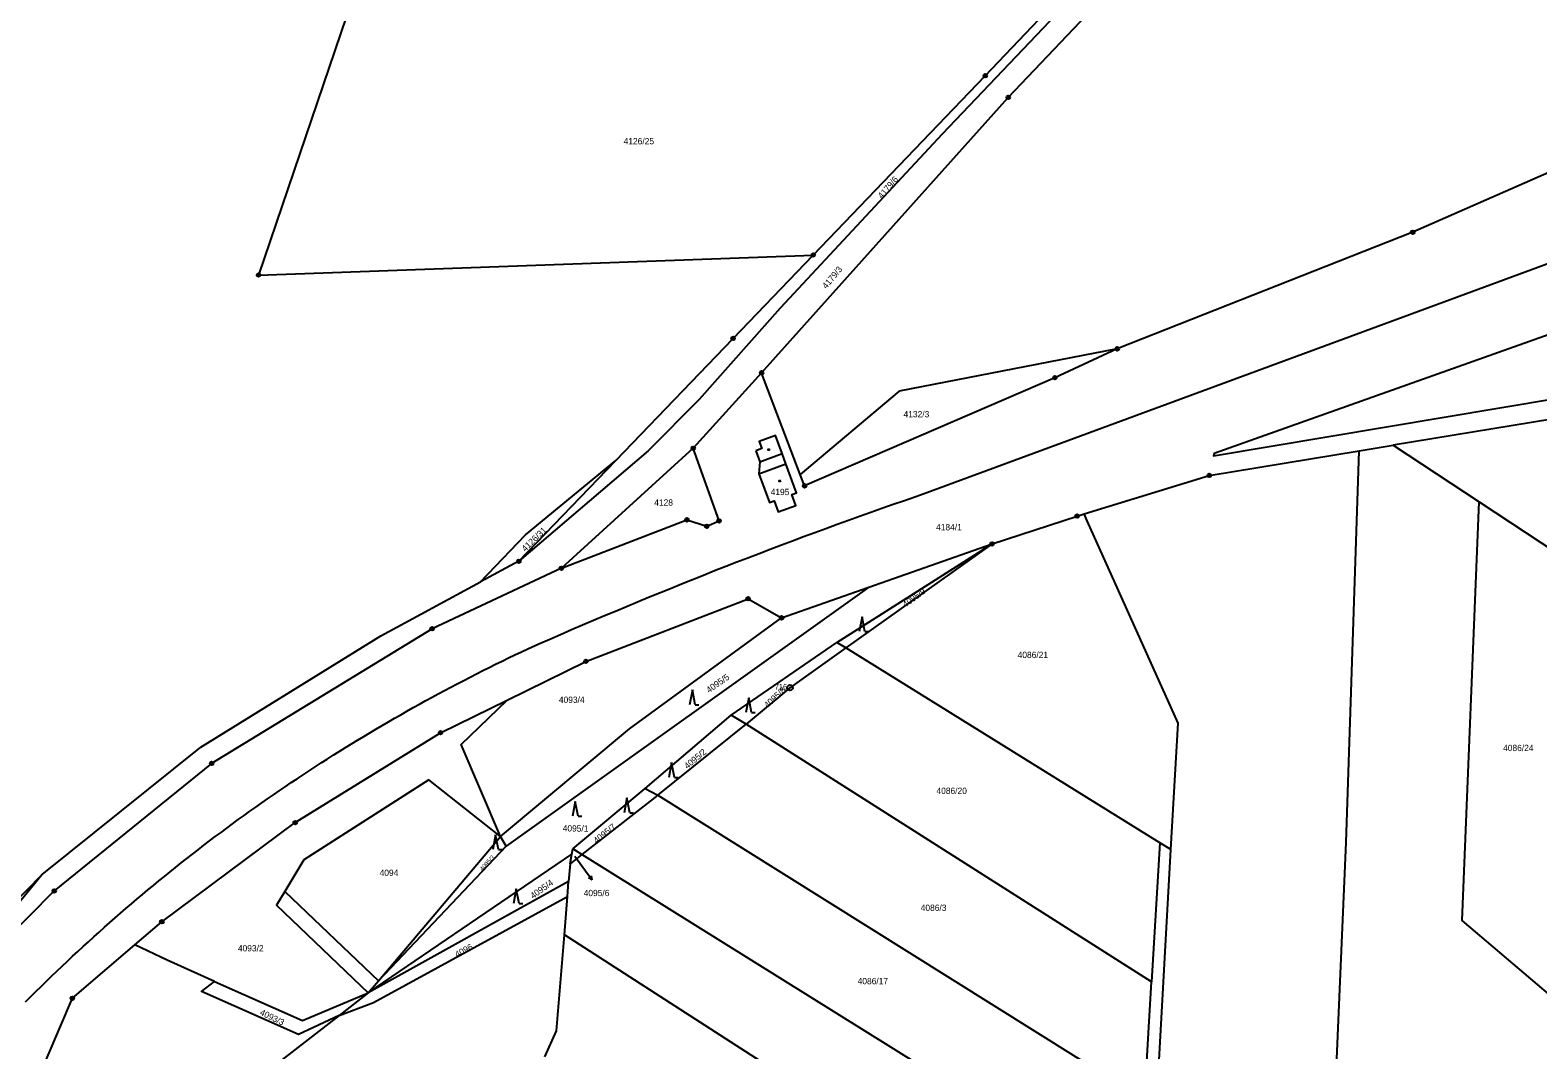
# Model space of a CAD drawing. Extents: x -733394 to -722299, y -1082822 to -1075049.
# Drawn here: x -729569.1 to -729161.7, y -1081847.7 to -1081571.9 of the extents above; entities that cross this region are included whole.
import ezdxf

# ---------------------------------------------------------------- set-up
doc = ezdxf.new("R2010")
doc.units = 0
for name, color, linetype in [('Hranice parcel', 7, 'Continuous'), ('Parcelní čísla', 7, 'Continuous'), ('Pop  PČ popisy', 7, 'Continuous'), ('Poz předměty', 7, 'Continuous'), ('Vnitřní kresba', 7, 'Continuous'), ('Značky bodu BP', 7, 'Continuous'), ('Značky budov', 7, 'Continuous'), ('Značky kultur', 7, 'Continuous')]:
    doc.layers.add(name, color=color, linetype=linetype)

msp = doc.modelspace()

# ---------------------------------------------------------------- linework, layer by layer
at = {"layer": 'Hranice parcel'}
for p, q in [((-729371.44, -1081664.57), (-729389.9, -1081684.99)), ((-729360.98, -1081692.11), (-729371.44, -1081664.57)), ((-729147.09, -1081675.32), (-729200.74, -1081684.15)), ((-729389.9, -1081684.99), (-729425.54, -1081717.43)), ((-729250.47, -1081692.34), (-729209.9, -1081685.66)), ((-729209.9, -1081685.66), (-729200.74, -1081684.15)), ((-729200.74, -1081684.15), (-729177.53, -1081699.5)), ((-729437.01, -1081715.56), (-729410.82, -1081688.29)), ((-729284.29, -1081702.76), (-729250.47, -1081692.34)), ((-729177.53, -1081699.5), (-729146.35, -1081720.13)), ((-729351.06, -1081737.52), (-729309.14, -1081710.85)), ((-729309.14, -1081710.85), (-729348.68, -1081739)), ((-729342.42, -1081722.55), (-729309.14, -1081710.85)), ((-729437.01, -1081715.56), (-729447.39, -1081721.16)), ((-729342.42, -1081722.55), (-729440.43, -1081792.62)), ((-729366.02, -1081730.85), (-729342.42, -1081722.55)), ((-729379.64, -1081757.19), (-729351.06, -1081737.52)), ((-729348.68, -1081739), (-729351.06, -1081737.52)), ((-729263.79, -1081791.67), (-729348.68, -1081739)), ((-729402.86, -1081777.01), (-729379.64, -1081757.19)), ((-729399.46, -1081778.81), (-729375.64, -1081759.59)), ((-729375.64, -1081759.59), (-729379.64, -1081757.19)), ((-729266.02, -1081829.3), (-729375.64, -1081759.59)), ((-729520.09, -1081770.22), (-729562.59, -1081804.71)), ((-729422.44, -1081793.36), (-729402.86, -1081777.01)), ((-729399.46, -1081778.81), (-729419.98, -1081794.89)), ((-729402.86, -1081777.01), (-729399.46, -1081778.81)), ((-729399.46, -1081778.81), (-729267.91, -1081861.15)), ((-729474.96, -1081828.97), (-729442.01, -1081790.02)), ((-729440.43, -1081792.62), (-729474.96, -1081828.97)), ((-729440.43, -1081792.62), (-729442.01, -1081790.02)), ((-729263.79, -1081791.67), (-729266.02, -1081829.3)), ((-729260.87, -1081793.48), (-729263.79, -1081791.67)), ((-729477.74, -1081832.25), (-729422.71, -1081794.79)), ((-729423.2, -1081797.41), (-729422.71, -1081794.79)), ((-729419.98, -1081794.89), (-729423.2, -1081797.41)), ((-729422.71, -1081794.79), (-729422.44, -1081793.36)), ((-729419.98, -1081794.89), (-729422.44, -1081793.36)), ((-729269.54, -1081888.64), (-729419.98, -1081794.89)), ((-729266.63, -1081899.59), (-729260.87, -1081793.48)), ((-729423.2, -1081797.41), (-729423.58, -1081802.17)), ((-729423.58, -1081802.17), (-729477.74, -1081832.25)), ((-729423.91, -1081806.25), (-729423.58, -1081802.17)), ((-729424.74, -1081816.55), (-729423.91, -1081806.25)), ((-729281.65, -1081908.79), (-729424.74, -1081816.55)), ((-729477.74, -1081832.25), (-729474.96, -1081828.97)), ((-729267.91, -1081861.15), (-729266.02, -1081829.3)), ((-729477.74, -1081832.25), (-729485.64, -1081838.38)), ((-729485.64, -1081838.38), (-729521.77, -1081866.42))]:
    msp.add_line(p, q, dxfattribs=at)
for points in [[(-729371.44, -1081664.57), (-729304.79, -1081590.12), (-729217.98, -1081498.78), (-729212.82, -1081482.72), (-729195.69, -1081383.64)], [(-729219.43, -1081482.86), (-729223.29, -1081496.17), (-729268.21, -1081542.86), (-729322.66, -1081600.05), (-729366.41, -1081647.14), (-729388.35, -1081671.83), (-729402.11, -1081685.74), (-729437.01, -1081715.56)], [(-728955.52, -1081524.35), (-728958.04, -1081525.39), (-729072.47, -1081572.57), (-729195.44, -1081626.58), (-729275.3, -1081658.11)], [(-729474.06, -1081539.95), (-729507.39, -1081638.15), (-729357.49, -1081632.74)], [(-729357.49, -1081632.74), (-729311, -1081584.27), (-729278.36, -1081549.84)], [(-729126.88, -1081658.24), (-729059.55, -1081636.73), (-729063.72, -1081620.5), (-729249.1, -1081686.45), (-729249.27, -1081687.01), (-729125.18, -1081666.25), (-729126.88, -1081658.24)], [(-729410.82, -1081688.29), (-729379.13, -1081655.3), (-729357.49, -1081632.74)], [(-729275.3, -1081658.11), (-729292.18, -1081665.91), (-729359.82, -1081695.16), (-729360.98, -1081692.11)], [(-729275.3, -1081658.11), (-729334.28, -1081669.53), (-729360.98, -1081692.11)], [(-729372.99, -1081685.69), (-729371.87, -1081688.68), (-729372.16, -1081691.92), (-729369.26, -1081699.71), (-729368.02, -1081699.25), (-729366.92, -1081702.21), (-729362.19, -1081700.44), (-729363.23, -1081697.47), (-729362, -1081697.01), (-729364.91, -1081689.21), (-729365.92, -1081686.46), (-729367.72, -1081681.58), (-729372.06, -1081683.2), (-729371.36, -1081685.07), (-729372.99, -1081685.69)], [(-729425.54, -1081717.43), (-729391.62, -1081704.35), (-729386.28, -1081706.1), (-729382.91, -1081704.64), (-729389.9, -1081684.99)], [(-729225.08, -1082061.1), (-729213.41, -1081791.58), (-729209.9, -1081685.66)], [(-729447.39, -1081721.16), (-729435.27, -1081708.4), (-729410.82, -1081688.29)], [(-729309.14, -1081710.85), (-729286.17, -1081703.34), (-729284.29, -1081702.76)], [(-729260.87, -1081793.48), (-729258.83, -1081759.33), (-729283.41, -1081704.6), (-729284.29, -1081702.76)], [(-729151.56, -1081838.69), (-729182.1, -1081812.72), (-729177.53, -1081699.5)], [(-729425.54, -1081717.43), (-729460.49, -1081733.82), (-729520.09, -1081770.22)], [(-729565.86, -1081800.28), (-729522.98, -1081765.86), (-729474.37, -1081735.71), (-729447.39, -1081721.16)], [(-729440.23, -1081753.09), (-729418.91, -1081742.62), (-729375.08, -1081725.68), (-729366.02, -1081730.85)], [(-729442.01, -1081790.02), (-729407.18, -1081760.91), (-729366.02, -1081730.85)], [(-729348.68, -1081739), (-729363.77, -1081749.74), (-729375.64, -1081759.59)], [(-729540.82, -1081819.28), (-729533.52, -1081813.03), (-729497.48, -1081786.24), (-729458.18, -1081761.91), (-729440.23, -1081753.09)], [(-729442.01, -1081790.02), (-729452.66, -1081765.14), (-729440.23, -1081753.09)], [(-729442.01, -1081790.02), (-729461.38, -1081774.69), (-729495.12, -1081796.26), (-729500.27, -1081804.82), (-729502.5, -1081808.52), (-729477.74, -1081832.25)], [(-729604.28, -1081845.42), (-729594.92, -1081829.92), (-729565.86, -1081800.28)], [(-729565.86, -1081800.28), (-729588.27, -1081827.56), (-729604.28, -1081845.42)], [(-729562.59, -1081804.71), (-729590.89, -1081833.28), (-729600.23, -1081846.76)], [(-729485.64, -1081838.38), (-729476.28, -1081834.87), (-729423.91, -1081806.25)], [(-729430.03, -1081849.6), (-729426.82, -1081842.49), (-729424.74, -1081816.55)], [(-729632.87, -1081946.37), (-729597.97, -1081923.36), (-729584.8, -1081903.48), (-729561.26, -1081883.19), (-729567.98, -1081857.76), (-729557.69, -1081833.72), (-729540.82, -1081819.28)], [(-729519.27, -1081829.16), (-729532.04, -1081823.44), (-729540.82, -1081819.28)], [(-729485.64, -1081838.38), (-729496.58, -1081843.53), (-729522.82, -1081831.89), (-729519.27, -1081829.16)], [(-729519.27, -1081829.16), (-729495.54, -1081839.78), (-729477.74, -1081832.25)]]:
    msp.add_lwpolyline(points, dxfattribs=at)
at = {"layer": 'Pop  PČ popisy'}
for p, q in [((-729421.92, -1081795.32), (-729419.02, -1081799.27)), ((-729419.02, -1081799.27), (-729417.26, -1081801.7)), ((-729417.26, -1081801.7), (-729418.25, -1081801.18)), ((-729417.26, -1081801.7), (-729417.44, -1081800.59))]:
    msp.add_line(p, q, dxfattribs=at)
at = {"layer": 'Poz předměty'}
msp.add_line((-729326.74, -1081696.99), (-728993.19, -1081573.72), dxfattribs=at)
for points in [[(-729434.58, -1081739.21), (-729431.64, -1081737.91), (-729428.69, -1081736.62), (-729425.74, -1081735.33), (-729422.79, -1081734.05), (-729419.83, -1081732.78), (-729416.87, -1081731.52), (-729413.91, -1081730.26), (-729410.94, -1081729.01), (-729407.97, -1081727.77), (-729405, -1081726.54), (-729402.03, -1081725.31), (-729399.05, -1081724.09), (-729396.07, -1081722.88), (-729393.09, -1081721.67), (-729390.1, -1081720.47), (-729387.11, -1081719.28), (-729384.12, -1081718.09), (-729381.12, -1081716.92), (-729378.12, -1081715.75), (-729375.12, -1081714.59), (-729372.12, -1081713.43), (-729369.11, -1081712.28), (-729366.1, -1081711.14), (-729363.09, -1081710.01), (-729360.08, -1081708.89), (-729357.06, -1081707.77), (-729354.04, -1081706.66), (-729351.02, -1081705.55), (-729347.99, -1081704.46), (-729344.96, -1081703.37), (-729341.93, -1081702.29), (-729338.9, -1081701.21), (-729335.86, -1081700.15), (-729332.83, -1081699.09), (-729329.78, -1081698.03), (-729326.74, -1081696.99)], [(-729559.05, -1081823.69), (-729557.64, -1081822.37), (-729556.22, -1081821.05), (-729554.79, -1081819.74), (-729553.36, -1081818.43), (-729551.93, -1081817.13), (-729550.49, -1081815.83), (-729549.04, -1081814.54), (-729547.59, -1081813.26), (-729546.14, -1081811.98), (-729544.68, -1081810.71), (-729543.21, -1081809.45), (-729541.74, -1081808.19), (-729540.26, -1081806.93), (-729538.78, -1081805.69), (-729537.3, -1081804.44), (-729535.8, -1081803.21), (-729534.31, -1081801.98), (-729532.81, -1081800.76), (-729531.3, -1081799.54), (-729529.79, -1081798.33), (-729528.27, -1081797.12), (-729526.75, -1081795.92), (-729525.23, -1081794.73), (-729523.69, -1081793.55), (-729522.16, -1081792.36), (-729520.62, -1081791.19), (-729519.07, -1081790.02), (-729517.52, -1081788.86), (-729515.97, -1081787.71), (-729514.41, -1081786.56), (-729512.85, -1081785.42), (-729511.28, -1081784.28), (-729509.7, -1081783.15), (-729508.12, -1081782.03), (-729506.54, -1081780.91), (-729504.96, -1081779.8), (-729503.36, -1081778.7), (-729501.77, -1081777.6), (-729500.17, -1081776.51), (-729498.56, -1081775.42), (-729496.96, -1081774.35), (-729495.34, -1081773.28), (-729493.72, -1081772.21), (-729492.1, -1081771.15), (-729490.48, -1081770.1), (-729488.85, -1081769.06), (-729487.21, -1081768.02), (-729485.57, -1081766.99), (-729483.93, -1081765.96), (-729482.28, -1081764.94), (-729480.63, -1081763.93), (-729478.97, -1081762.93), (-729477.31, -1081761.93), (-729475.65, -1081760.94), (-729473.98, -1081759.95), (-729472.31, -1081758.97), (-729470.63, -1081758), (-729468.96, -1081757.04), (-729467.27, -1081756.08), (-729465.58, -1081755.13), (-729463.89, -1081754.19), (-729462.2, -1081753.25), (-729460.5, -1081752.32), (-729458.8, -1081751.4), (-729457.09, -1081750.48), (-729455.38, -1081749.57), (-729453.67, -1081748.67), (-729451.95, -1081747.78), (-729450.23, -1081746.89), (-729448.5, -1081746.01), (-729446.78, -1081745.13), (-729445.04, -1081744.27), (-729443.31, -1081743.4), (-729441.57, -1081742.55), (-729439.83, -1081741.71), (-729438.08, -1081740.87), (-729436.33, -1081740.04), (-729434.58, -1081739.21)], [(-729570.38, -1081834.69), (-729568.98, -1081833.3), (-729567.58, -1081831.91), (-729566.17, -1081830.52), (-729564.76, -1081829.15), (-729563.34, -1081827.77), (-729561.92, -1081826.41), (-729560.48, -1081825.05), (-729559.05, -1081823.69)]]:
    msp.add_lwpolyline(points, dxfattribs=at)
at = {"layer": 'Vnitřní kresba'}
for p, q in [((-729371.87, -1081688.68), (-729365.92, -1081686.46)), ((-729372.16, -1081691.92), (-729364.91, -1081689.21)), ((-729500.27, -1081804.82), (-729474.96, -1081828.97))]:
    msp.add_line(p, q, dxfattribs=at)
at = {"layer": 'Značky bodu BP'}
for centre, radius in [((-729311, -1081584.27), 0.5), ((-729311, -1081584.27), 0.0303), ((-729304.79, -1081590.12), 0.5), ((-729304.79, -1081590.12), 0.0303), ((-729195.44, -1081626.58), 0.5), ((-729195.44, -1081626.58), 0.0303), ((-729357.49, -1081632.74), 0.5), ((-729357.49, -1081632.74), 0.0303), ((-729507.39, -1081638.15), 0.5), ((-729507.39, -1081638.15), 0.0303), ((-729379.13, -1081655.3), 0.5), ((-729379.13, -1081655.3), 0.0303), ((-729275.3, -1081658.11), 0.5), ((-729275.3, -1081658.11), 0.0303), ((-729371.44, -1081664.57), 0.5), ((-729371.44, -1081664.57), 0.0303), ((-729292.18, -1081665.91), 0.5), ((-729292.18, -1081665.91), 0.0303), ((-729389.9, -1081684.99), 0.5), ((-729389.9, -1081684.99), 0.0303), ((-729359.82, -1081695.16), 0.5), ((-729359.82, -1081695.16), 0.0303), ((-729250.47, -1081692.34), 0.5), ((-729250.47, -1081692.34), 0.0303), ((-729286.17, -1081703.34), 0.5), ((-729286.17, -1081703.34), 0.0303), ((-729391.62, -1081704.35), 0.5), ((-729391.62, -1081704.35), 0.0303), ((-729386.28, -1081706.1), 0.5), ((-729386.28, -1081706.1), 0.0303), ((-729382.91, -1081704.64), 0.5), ((-729382.91, -1081704.64), 0.0303), ((-729309.14, -1081710.85), 0.5), ((-729309.14, -1081710.85), 0.0303), ((-729437.01, -1081715.56), 0.5), ((-729437.01, -1081715.56), 0.0303), ((-729425.54, -1081717.43), 0.5), ((-729425.54, -1081717.43), 0.0303), ((-729375.08, -1081725.68), 0.5), ((-729375.08, -1081725.68), 0.0303), ((-729366.02, -1081730.85), 0.5), ((-729366.02, -1081730.85), 0.0303), ((-729460.49, -1081733.82), 0.5), ((-729460.49, -1081733.82), 0.0303), ((-729418.91, -1081742.62), 0.5), ((-729418.91, -1081742.62), 0.0303), ((-729363.77, -1081749.74), 0.75), ((-729363.77, -1081749.74), 0.03), ((-729458.18, -1081761.91), 0.5), ((-729458.18, -1081761.91), 0.0303), ((-729520.09, -1081770.22), 0.5), ((-729520.09, -1081770.22), 0.0303), ((-729497.48, -1081786.24), 0.5), ((-729497.48, -1081786.24), 0.0303), ((-729562.59, -1081804.71), 0.5), ((-729562.59, -1081804.71), 0.0303), ((-729533.52, -1081813.03), 0.5), ((-729533.52, -1081813.03), 0.0303), ((-729557.69, -1081833.72), 0.5), ((-729557.69, -1081833.72), 0.0303)]:
    msp.add_circle(centre, radius, dxfattribs=at)
at = {"layer": 'Značky budov'}
for centre in [(-729369.51, -1081685.38), (-729366.54, -1081693.85)]:
    msp.add_circle(centre, 0.175, dxfattribs=at)
at = {"layer": 'Značky kultur'}
for p, q in [((-729344.29, -1081730.59), (-729345.04, -1081734.59)), ((-729343.54, -1081734.59), (-729344.29, -1081730.59)), ((-729343.54, -1081734.59), (-729342.54, -1081734.59)), ((-729390.14, -1081750.34), (-729390.89, -1081754.34)), ((-729389.39, -1081754.34), (-729390.14, -1081750.34)), ((-729389.39, -1081754.34), (-729388.39, -1081754.34)), ((-729374.91, -1081752.46), (-729375.66, -1081756.46)), ((-729374.16, -1081756.46), (-729374.91, -1081752.46)), ((-729374.16, -1081756.46), (-729373.16, -1081756.46)), ((-729395.76, -1081770), (-729396.51, -1081774)), ((-729395.01, -1081774), (-729395.76, -1081770)), ((-729395.01, -1081774), (-729394.01, -1081774)), ((-729421.8, -1081780.52), (-729422.55, -1081784.52)), ((-729421.05, -1081784.52), (-729421.8, -1081780.52)), ((-729407.82, -1081779.54), (-729408.57, -1081783.54)), ((-729407.07, -1081783.54), (-729407.82, -1081779.54)), ((-729421.05, -1081784.52), (-729420.05, -1081784.52)), ((-729407.07, -1081783.54), (-729406.07, -1081783.54)), ((-729443.33, -1081789.52), (-729444.08, -1081793.52)), ((-729442.58, -1081793.52), (-729443.33, -1081789.52)), ((-729442.58, -1081793.52), (-729441.58, -1081793.52)), ((-729437.74, -1081804.12), (-729438.49, -1081808.12)), ((-729436.99, -1081808.12), (-729437.74, -1081804.12)), ((-729436.99, -1081808.12), (-729435.99, -1081808.12))]:
    msp.add_line(p, q, dxfattribs=at)

# ---------------------------------------------------------------- texts
at = {"layer": 'Parcelní čísla'}
for s, p in [('4126/25', (-729408.72, -1081602.82)), ('4132/3', (-729333.07, -1081676.63)), ('4128', (-729400.45, -1081700.53)), ('4195', (-729368.99, -1081697.67)), ('4184/1', (-729324.28, -1081707.19)), ('4086/21', (-729302.24, -1081741.72)), ('4093/4', (-729426.22, -1081753.85)), ('4086/24', (-729171.04, -1081766.89)), ('4086/20', (-729324.17, -1081778.47)), ('4094', (-729474.67, -1081800.64)), ('4095/6', (-729419.52, -1081806.11)), ('4086/3', (-729328.43, -1081810.1)), ('4093/2', (-729512.97, -1081821.06)), ('4086/17', (-729345.48, -1081829.93))]:
    msp.add_text(s, height=1.7, dxfattribs=at).set_placement(p)
for s, height, rotation, p in [('4179/6', 1.7, 49, (-729338.93, -1081617.64)), ('4179/3', 1.7, 50, (-729353.95, -1081642.02)), ('4126/31', 1.7, 44, (-729435.29, -1081713.06)), ('4095/9', 1.7, 36, (-729332.57, -1081728.11)), ('4095/5', 1.7, 35, (-729385.66, -1081751.27)), ('4095/8', 1.7, 43, (-729369.83, -1081755.38)), ('4095/2', 1.7, 40, (-729391.5, -1081771.85)), ('4095/1', 1.7, 359, (-729425.2, -1081788.59)), ('4095/7', 1.7, 39, (-729416.05, -1081792.03)), ('4095/3', 1.19, 47, (-729446.89, -1081799.41)), ('4095/4', 1.7, 36, (-729433.19, -1081806.94)), ('4096', 1.7, 29, (-729453.72, -1081822.79)), ('4093/3', 1.7, 334, (-729507.21, -1081838.13))]:
    msp.add_text(s, height=height, rotation=rotation, dxfattribs=at).set_placement(p)
at = {"layer": 'Značky bodu BP'}
msp.add_text('716', height=1.5, dxfattribs=at).set_placement((-729367.87, -1081750.24))

doc.saveas('drawing.dxf')
